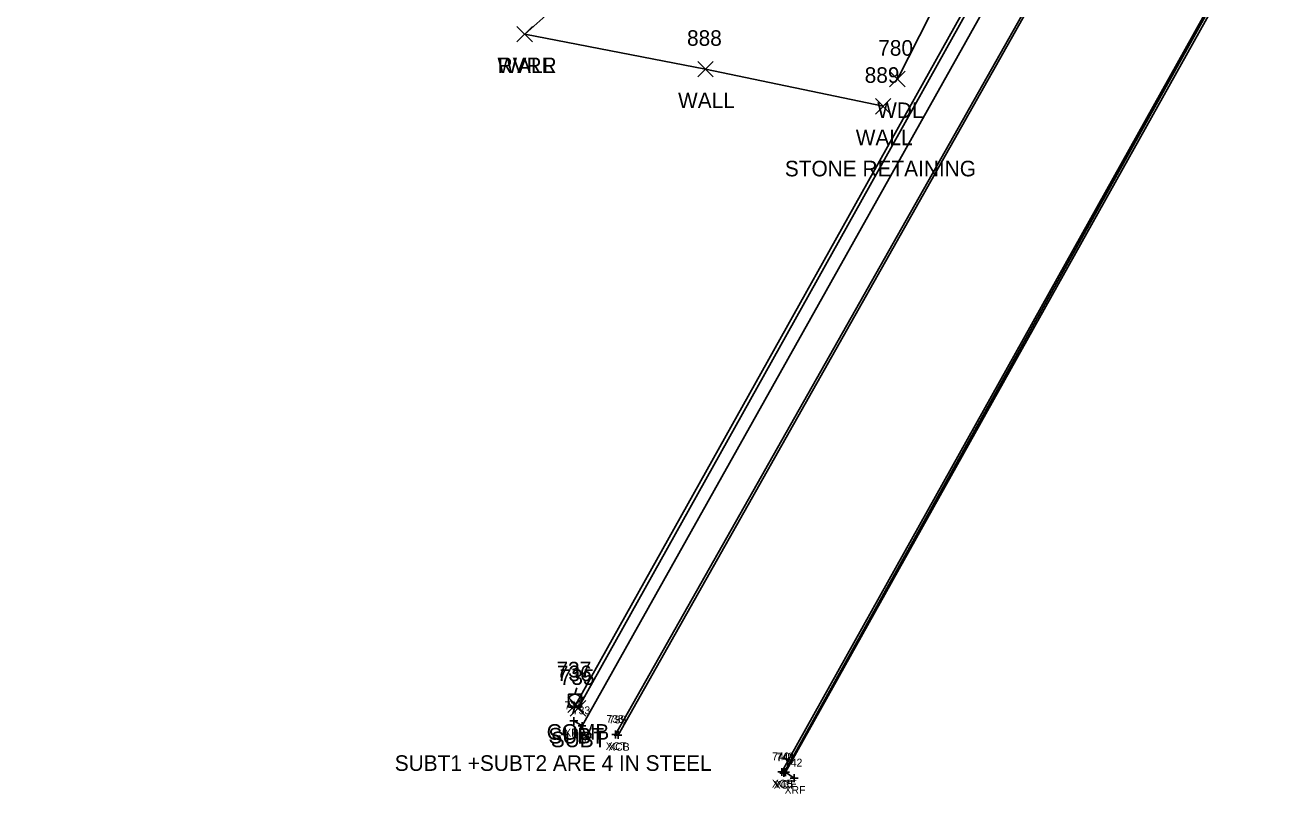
# Model space of a CAD drawing. Extents: x 1764889 to 1767296, y 695936 to 698960.
# Drawn here: x 1766171.9 to 1766333.8, y 696228.3 to 696326.9 of the extents above; entities that cross this region are included whole.
import ezdxf

# ---------------------------------------------------------------- set-up
doc = ezdxf.new("R2010")
doc.units = 0
for name, color, linetype in [('B_A', 7, 'Continuous'), ('B_I', 7, 'Continuous'), ('B_TIC', 7, 'Continuous'), ('BDC', 7, 'Continuous'), ('BR', 7, 'Continuous'), ('L_A', 7, 'Continuous'), ('L_C', 7, 'Continuous'), ('L_I', 7, 'Continuous'), ('L_TIC', 7, 'Continuous'), ('LAWA', 7, 'Continuous'), ('LAWE', 7, 'Continuous'), ('LW', 7, 'Continuous'), ('U_A', 7, 'Continuous'), ('U_C', 7, 'Continuous'), ('U_I', 7, 'Continuous'), ('U_TIC', 7, 'Continuous'), ('UP', 7, 'Continuous'), ('UT', 7, 'Continuous')]:
    doc.layers.add(name, color=color, linetype=linetype)

msp = doc.modelspace()

# ---------------------------------------------------------------- linework, layer by layer
at = {"layer": 'B_TIC'}
for p, q in [((1766242.22, 696237.68), (1766242.3, 696237.68)), ((1766243.27, 696237.04), (1766243.35, 696237.04)), ((1766247.59, 696235.94), (1766247.66, 696235.94)), ((1766247.9, 696235.86), (1766247.98, 696235.86)), ((1766268.89, 696231.13), (1766268.97, 696231.13)), ((1766269.14, 696230.99), (1766269.22, 696230.99)), ((1766269.37, 696231.11), (1766269.45, 696231.11)), ((1766270.49, 696230.33), (1766270.56, 696230.33))]:
    msp.add_line(p, q, dxfattribs=at)
for points in [[(1766242.22, 696237.18), (1766242.22, 696238.18)], [(1766241.72, 696237.68), (1766242.72, 696237.68)], [(1766242.77, 696237.04), (1766243.77, 696237.04)], [(1766243.27, 696236.54), (1766243.27, 696237.54)], [(1766247.58, 696235.44), (1766247.58, 696236.44)], [(1766247.08, 696235.94), (1766248.08, 696235.94)], [(1766247.4, 696235.86), (1766248.4, 696235.86)], [(1766247.9, 696235.36), (1766247.9, 696236.36)], [(1766268.89, 696230.63), (1766268.89, 696231.63)], [(1766269.37, 696230.61), (1766269.37, 696231.61)], [(1766268.39, 696231.13), (1766269.39, 696231.13)], [(1766268.64, 696230.99), (1766269.64, 696230.99)], [(1766268.87, 696231.11), (1766269.87, 696231.11)], [(1766269.14, 696230.49), (1766269.14, 696231.49)], [(1766269.99, 696230.33), (1766270.99, 696230.33)], [(1766270.49, 696229.83), (1766270.49, 696230.83)]]:
    msp.add_lwpolyline(points, dxfattribs=at)
at = {"layer": 'BDC'}
for points in [[(1766311.75, 696349.59), (1766247.58, 696235.94)], [(1766312, 696349.5), (1766247.9, 696235.86)], [(1766268.89, 696231.13), (1766332.15, 696344.53), (1766333.8, 696343.8)], [(1766269.14, 696230.99), (1766332.24, 696344.32), (1766333.74, 696343.56)]]:
    msp.add_lwpolyline(points, dxfattribs=at)
at = {"layer": 'BR'}
for points in [[(1766305.11, 696350.62), (1766306.49, 696349.77), (1766243.27, 696237.04), (1766242.22, 696237.68)], [(1766270.49, 696230.33), (1766269.37, 696231.11), (1766332.32, 696343.76), (1766333.42, 696343.16)]]:
    msp.add_lwpolyline(points, dxfattribs=at)
at = {"layer": 'L_TIC'}
for points in [[(1766234.93, 696324.79), (1766236.93, 696326.79)], [(1766236.93, 696324.79), (1766234.93, 696326.79)], [(1766234.93, 696324.79), (1766236.93, 696326.79)], [(1766236.93, 696324.79), (1766234.93, 696326.79)], [(1766258.11, 696320.3), (1766260.11, 696322.3)], [(1766260.11, 696320.3), (1766258.11, 696322.3)], [(1766282.72, 696319.03), (1766284.72, 696321.03)], [(1766284.72, 696319.03), (1766282.72, 696321.03)], [(1766280.9, 696315.55), (1766282.9, 696317.55)], [(1766282.9, 696315.55), (1766280.9, 696317.55)]]:
    msp.add_lwpolyline(points, dxfattribs=at)
at = {"layer": 'LAWA'}
msp.add_lwpolyline([(1766283.72, 696320.03), (1766290.85, 696334.04), (1766299.68, 696349.64), (1766296.46, 696353.04), (1766287.49, 696358.7), (1766296.79, 696389.3)], dxfattribs=at)
at = {"layer": 'LAWE'}
msp.add_lwpolyline([(1766171.85, 696351.54), (1766197.96, 696351.7), (1766219.32, 696343.87), (1766233.88, 696343.92), (1766243.23, 696332.33), (1766235.93, 696325.79)], dxfattribs=at)
at = {"layer": 'LW'}
msp.add_lwpolyline([(1766235.93, 696325.79), (1766259.11, 696321.3), (1766281.9, 696316.55)], dxfattribs=at)
at = {"layer": 'U_TIC'}
for points in [[(1766241.47, 696238.78), (1766243.47, 696240.78)], [(1766243.47, 696238.78), (1766241.47, 696240.78)], [(1766241.77, 696238.3), (1766243.77, 696240.3)], [(1766243.77, 696238.3), (1766241.77, 696240.3)]]:
    msp.add_lwpolyline(points, dxfattribs=at)
at = {"layer": 'UP'}
for p, q in [((1766242.61, 696241.94), (1766242.36, 696241.11)), ((1766241.52, 696239.44), (1766241.52, 696241.11)), ((1766241.52, 696241.11), (1766243.19, 696241.11)), ((1766242.36, 696240.27), (1766242.36, 696240.27)), ((1766243.19, 696241.11), (1766243.19, 696239.44)), ((1766243.19, 696239.44), (1766241.52, 696239.44)), ((1766242.11, 696238.61), (1766242.36, 696239.44))]:
    msp.add_line(p, q, dxfattribs=at)
msp.add_circle((1766242.36, 696240.27), 0.833, dxfattribs=at)
at = {"layer": 'UT'}
for points in [[(1766303.75, 696349.5), (1766242.47, 696239.78)], [(1766304.18, 696349.36), (1766242.77, 696239.3)]]:
    msp.add_lwpolyline(points, dxfattribs=at)

# ---------------------------------------------------------------- texts
at = {"layer": 'B_A'}
for s, p in [('XRF', (1766240.98, 696235.68)), ('XRF', (1766242.03, 696235.04)), ('XCT', (1766246.31, 696233.94)), ('XCB', (1766246.64, 696233.86)), ('XCB', (1766267.63, 696229.13)), ('XCT', (1766267.86, 696228.99)), ('XRF', (1766268.13, 696229.11)), ('XRF', (1766269.25, 696228.33))]:
    msp.add_text(s, height=1, dxfattribs=at).set_placement(p)
at = {"layer": 'B_I'}
for s, p in [('734', (1766241.04, 696239.18)), ('733', (1766242.09, 696238.54)), ('738', (1766246.4, 696237.44)), ('739', (1766246.71, 696237.36)), ('740', (1766267.66, 696232.63)), ('743', (1766268.19, 696232.61)), ('741', (1766268.24, 696232.49)), ('742', (1766269.3, 696231.83))]:
    msp.add_text(s, height=1, dxfattribs=at).set_placement(p)
at = {"layer": 'L_A'}
for s, p in [('WALL', (1766232.42, 696320.79)), ('RVRR', (1766232.44, 696320.79)), ('WALL', (1766255.59, 696316.3)), ('WDL', (1766281.13, 696315.03)), ('WALL', (1766278.39, 696311.55))]:
    msp.add_text(s, height=2, dxfattribs=at).set_placement(p)
at = {"layer": 'L_C'}
msp.add_text('STONE RETAINING', height=2, dxfattribs=at).set_placement((1766269.29, 696307.55))
at = {"layer": 'L_I'}
for s, p in [('888', (1766256.74, 696324.3)), ('780', (1766281.27, 696323.03)), ('889', (1766279.53, 696319.55))]:
    msp.add_text(s, height=2, dxfattribs=at).set_placement(p)
at = {"layer": 'U_A'}
for s, p in [('COMB', (1766238.74, 696235.27)), ('SUBT', (1766238.96, 696234.78)), ('SUBT', (1766239.27, 696234.3))]:
    msp.add_text(s, height=2, dxfattribs=at).set_placement(p)
at = {"layer": 'U_C'}
msp.add_text('SUBT1 +SUBT2 ARE 4 IN STEEL', height=2, dxfattribs=at).set_placement((1766219.25, 696231.27))
at = {"layer": 'U_I'}
for s, p in [('737', (1766239.99, 696243.27)), ('736', (1766240.05, 696242.78)), ('735', (1766240.41, 696242.3))]:
    msp.add_text(s, height=2, dxfattribs=at).set_placement(p)

doc.saveas('drawing.dxf')
